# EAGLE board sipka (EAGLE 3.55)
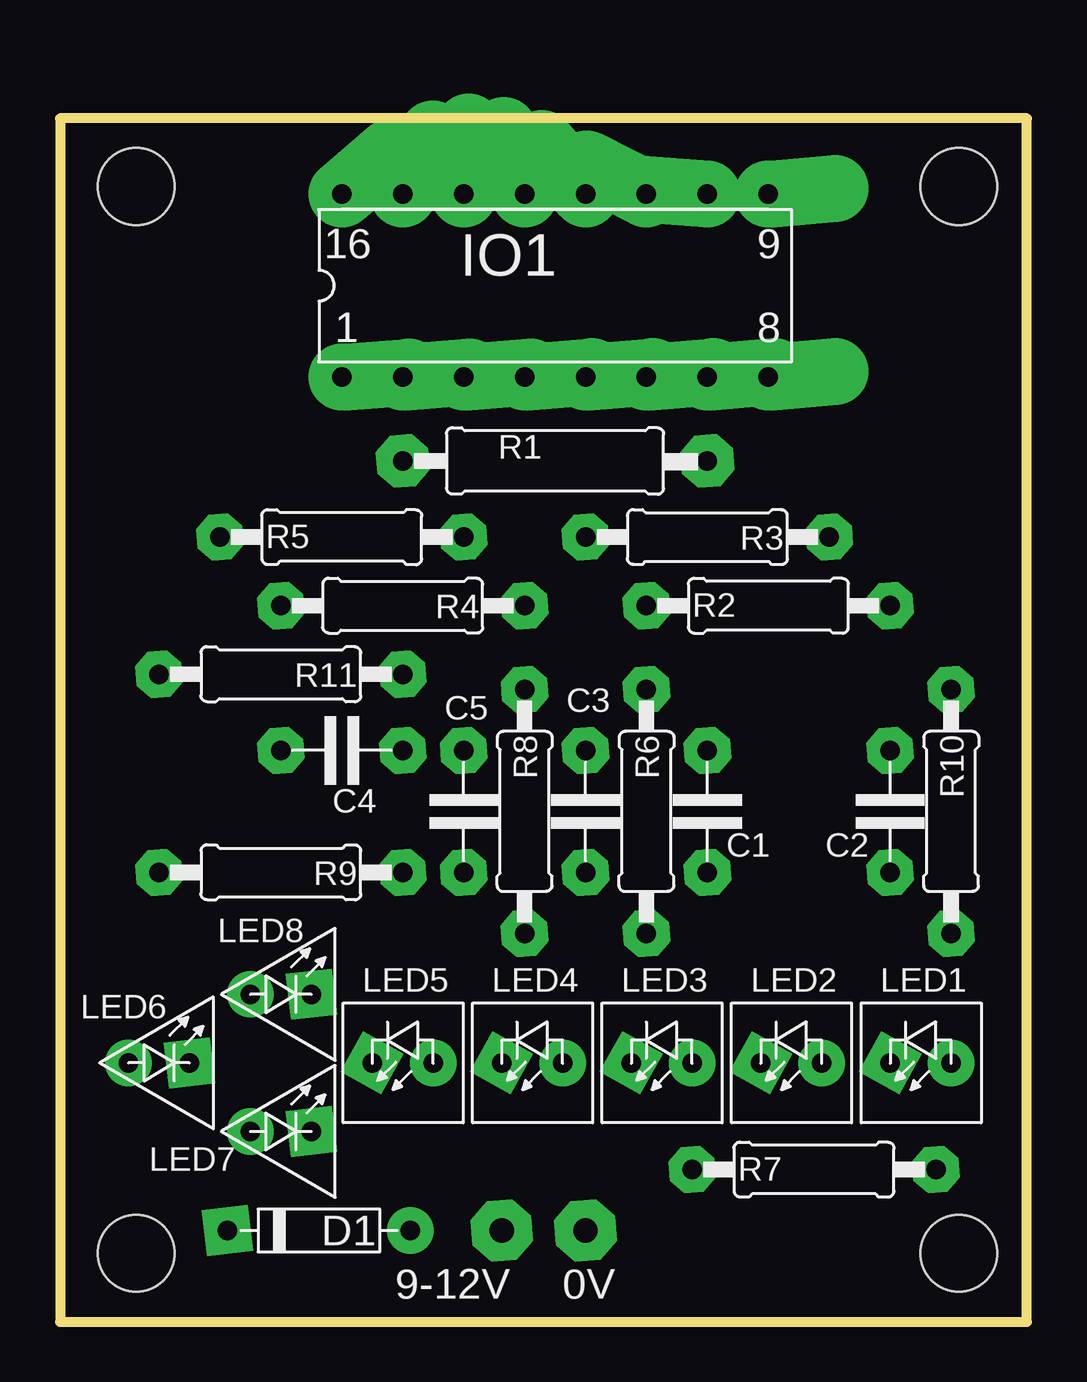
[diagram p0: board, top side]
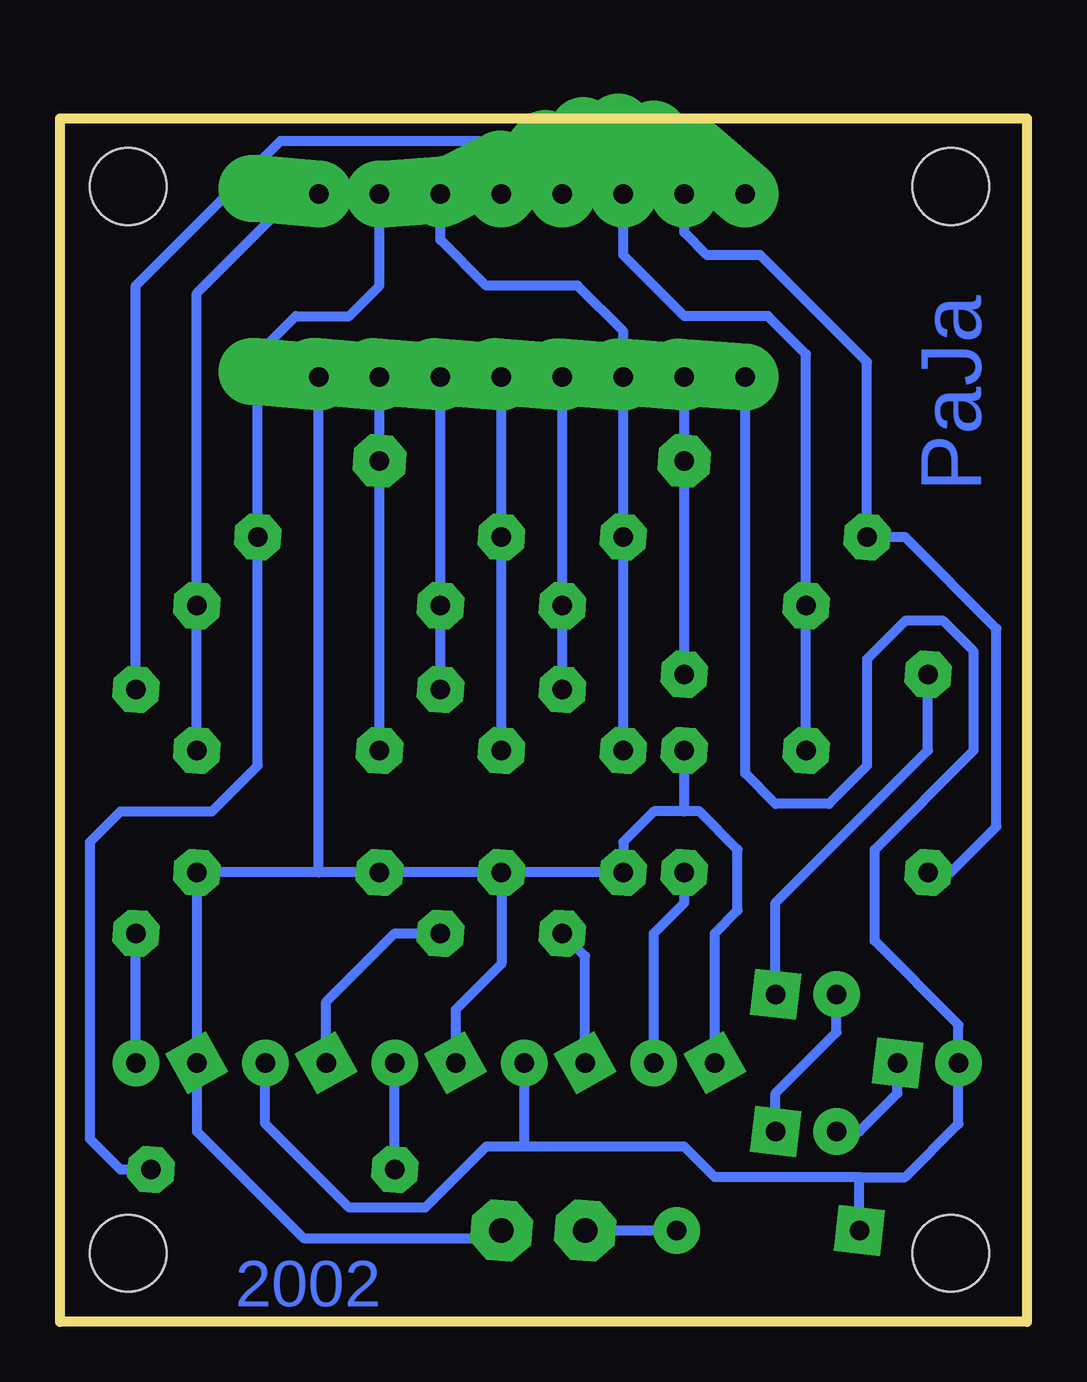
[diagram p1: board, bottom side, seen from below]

Size 40.31 x 50.15 mm. Coordinates in mm from the lower left corner, seen from the top.
Outline: 0,0 40.31,0 40.31,50.15 0,50.15 0,0
Copper layers used: Bottom
Holes 3.2 mm at 3.18,2.86 3.18,47.31 37.46,47.31 37.46,2.86

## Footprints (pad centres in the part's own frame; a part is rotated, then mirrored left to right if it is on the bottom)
D 1 = drill 1.016 pad 2.54 octagon:  0,0
5 = drill 0.813 pad 1.93 octagon:  -2.54,0;  2.54,0
7,5 = drill 0.813 pad 1.93 square:  3.81,0 | drill 0.813 pad 1.93 round:  -3.81,0
L16 = drill 0.813 pad 2.8 offset:  -8.89,-3.81;  -6.35,-3.81;  -3.81,-3.81;  -1.27,-3.81;  1.27,-3.81;  3.81,-3.81;  6.35,-3.81;  8.89,-3.81;  8.89,3.81;  6.35,3.81;  3.81,3.81;  1.27,3.81;  -1.27,3.81;  -3.81,3.81;  -6.35,3.81;  -8.89,3.81
D 5X5 = drill 0.813 pad 1.93 square:  0,0 | drill 0.813 pad 1.93 round:  -2.54,0
D TROJ = drill 0.813 pad 1.93 square:  -1.27,0 | drill 0.813 pad 1.93 round:  1.27,0
12,7 = drill 0.813 pad 2.184 octagon:  -6.35,0;  6.35,0
10 = drill 0.813 pad 1.93 octagon:  -5.08,0;  5.08,0

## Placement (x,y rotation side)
0V  PAD  [D 1]  21.91,3.81 0 top
9-12V  PAD  [D 1]  18.42,3.81 0 top
C1  100n  [5]  26.99,21.27 90 top
C2  100n  [5]  34.61,21.27 90 top
C3  100n  [5]  21.91,21.27 90 top
C4  100n  [5]  11.75,23.81 180 top
C5  100n  [5]  16.83,21.27 90 top
D1  1N4148  [7,5]  10.79,3.81 180 top
IO1  4049  [L16]  20.64,43.18 0 top
LED1  cer  [D 5X5]  34.61,10.79 180 top
LED2  cer  [D 5X5]  29.21,10.79 180 top
LED3  cer  [D 5X5]  23.81,10.79 180 top
LED4  cer  [D 5X5]  18.42,10.79 180 top
LED5  cer  [D 5X5]  13.02,10.79 180 top
LED6  cer  [D TROJ]  4.13,10.79 180 top
LED7  cer  [D TROJ]  9.21,7.94 180 top
LED8  cer  [D TROJ]  9.21,13.65 180 top
R1  2M2  [12,7]  20.64,35.88 0 top
R2  2M2  [10]  29.53,29.85 0 top
R3  2M2  [10]  26.99,32.7 180 top
R4  2M2  [10]  14.29,29.85 180 top
R5  2M2  [10]  11.75,32.7 0 top
R6  390  [10]  24.45,21.27 270 top
R7  390  [10]  31.43,6.35 0 top
R8  390  [10]  19.37,21.27 270 top
R9  390  [10]  9.21,18.73 180 top
R10  390  [10]  37.15,21.27 270 top
R11  330  [10]  9.21,26.99 180 top

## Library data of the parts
0V 9-12V C1-C5 D1 IO1 LED1-LED8 R1-R11 = 1_PaJa_8

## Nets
+VCC: D1. IO1. LED2. LED4. LED6.
GND: 0V. C1. C2. C3. C4. C5. IO1. LED1. LED3. LED5.
N$1: IO1. R1. R11.
N$2: LED7. LED8.
N$3: LED6. LED7.
N$4: LED8. R11.
N$5: LED2. R6.
N$6: LED5. R9.
N$7: IO1. R2. R6.
N$8: C1. IO1. R1.
N$9: C2. IO1. R2.
N$10: IO1. R3. R7.
N$11: C3. IO1. R3.
N$12: IO1. R4. R8.
N$13: C4. IO1. R4.
N$14: IO1. R5. R9.
N$15: C5. IO1. R5.
N$16: LED4. R8.
N$17: 9-12V. D1.
N$18: LED3. R7.
N$19: LED1. R10.
N$28: IO1. R10.

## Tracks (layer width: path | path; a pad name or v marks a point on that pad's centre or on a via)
+VCC
  Bottom 0.406: 11.75,39.37 11.75,22.86 10.48,21.59 8.25,21.59 6.67,23.18 6.67,27.62 5.08,29.21 3.49,29.21 2.22,27.94 2.22,23.81 6.35,19.69 6.35,15.87 2.86,12.38 LED6. 2.86,8.25 5.08,6.03 6.99,6.03 | LED2. 31.75,8.25 28.26,4.76 25.08,4.76 22.54,7.3 20.96,7.3 | 6.99,6.03 13.02,6.03 14.29,7.3 20.96,7.3 | 20.96,7.3 LED4. | 6.99,3.81 6.99,6.03
GND
  Bottom 0.406: 29.53,18.73 26.99,18.73 21.91,18.73 | 29.53,18.73 34.61,18.73 34.61,10.8 34.61,7.94 30.16,3.49 22.23,3.49 0V. | 21.91,18.73 16.83,18.73 16.83,20 15.56,21.27 14.29,21.27 | 29.53,18.73 29.53,39.37 | 23.81,10.8 23.81,13.02 21.91,14.92 21.91,18.73 | 13.02,10.8 13.02,16.19 12.07,17.14 12.07,19.69 13.65,21.27 14.29,21.27 | 14.29,21.27 14.29,23.81
N$1
  Bottom 0.406: 14.29,39.37 14.29,35.88 14.29,26.99
N$2
  Bottom 0.406: LED8. 7.94,12.07 10.48,9.52 10.48,7.94
N$3
  Bottom 0.406: 5.4,10.8 5.4,9.52 6.99,7.94 LED7.
N$4
  Bottom 0.406: 10.48,13.65 10.48,17.46 4.13,23.81 R11.
N$5
  Bottom 0.406: 29.21,10.8 29.21,13.33 26.35,16.19 R6.
N$6
  Bottom 0.406: LED5. 15.56,16.19 14.29,17.46 14.29,18.73
N$7
  Bottom 0.406: 24.45,39.37 24.45,29.85 24.45,26.35
N$8
  Bottom 0.406: 26.99,39.37 R1. C1.
N$9
  Bottom 0.406: C2. R2. 34.61,42.86 30.48,46.99 29.53,46.99
N$10
  Bottom 0.406: 26.99,46.99 26.99,43.18 28.26,41.91 30.48,41.91 32.07,40.32 32.07,32.7 32.07,23.18 33.97,21.27 37.78,21.27 39.05,20 39.05,7.62 37.78,6.35 R7.
N$11
  Bottom 0.406: 21.91,39.37 R3. C3.
N$12
  Bottom 0.406: 19.37,39.37 19.37,29.85 19.37,26.35
N$13
  Bottom 0.406: C4. R4. 9.21,40.32 10.8,41.91 14.29,41.91 16.83,44.45 16.83,46.99
N$14
  Bottom 0.406: 14.29,46.99 14.29,45.4 13.33,44.45 11.11,44.45 6.67,40 6.67,32.7 5.08,32.7 1.27,28.89 1.27,20.64 3.18,18.73 R9.
N$15
  Bottom 0.406: C5. R5. 16.83,39.37 16.83,41.28 18.73,43.18 22.54,43.18 24.45,45.09 24.45,46.99
N$16
  Bottom 0.406: 18.42,10.8 18.42,15.24 R8.
N$17
  Bottom 0.406: D1. 9-12V.
N$18
  Bottom 0.406: 26.35,6.35 LED3.
N$19
  Bottom 0.406: LED1. R10.
N$28
  Bottom 0.406: 21.91,46.99 21.91,48.26 22.86,49.21 31.12,49.21 37.15,43.18 37.15,26.35

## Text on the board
Bottom: PaJa | 2002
